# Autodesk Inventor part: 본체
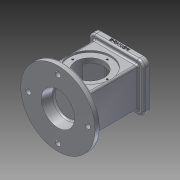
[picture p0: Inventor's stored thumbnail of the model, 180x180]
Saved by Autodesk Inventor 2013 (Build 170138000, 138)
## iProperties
Created: 2018-10
Part Number: 본체
Material: 알루미늄 6061
Document SubType Name: Modeling
Designer: Administrator
Density: 2.71 g/cm^3
Mass: 989.33 g
Surface Area: 739.56 cm^2
Volume: 365.066 cm^3
Author: Administrator
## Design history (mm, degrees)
sketch "스케치1"
  geometry: L1 (-37, -33)-(37, -33); L2 (37, -33)-(37, 33); L3 (37, 33)-(-37, 33); L4 (-37, 33)-(-37, -33); L5 (-37, -33)-(37, 33); L6 (37, -33)-(-37, 33); 1 further point
  constraints: 12 end point, 2 midpoint, 2 parallel, 1 horizontal, 1 perpendicular
  dimensions: "d1" = 74 distance of L3.end L2.end; "d2" = 66 distance of L2.end L1.end
extrude "돌출1" new body sketch "스케치1" distance "d3" = 108; taper "d4" = 0 deg
sketch "스케치2"
  geometry: L1 (37, -33)-(-37, -33) reference; L2 (37, 33)-(37, -33) reference; L3 (-37, 33)-(37, 33) reference; L4 (-37, -33)-(-37, 33) reference; C1 r 62.5 at (0, 0); 1 further point
  constraints: 1 centre point, 1 coincident
  dimensions: "d5" = 125 diameter of C1
extrude "돌출2" join sketch "스케치2" distance "d6" = 10; taper "d7" = 0 deg
sketch "스케치3"
  geometry: L1 (37, 33)-(-37, 33) reference; L2 (-37, 33)-(-37, -33) reference; L3 (-37, -33)-(37, -33) reference; L4 (37, -33)-(37, 33) reference; L5 (-46, -41)-(46, -41); L6 (46, -41)-(46, 41); L7 (46, 41)-(-46, 41); L8 (-46, 41)-(-46, -41); L9 (-46, -41)-(46, 41); L10 (46, -41)-(-46, 41); 1 further point
  constraints: 12 end point, 2 midpoint, 2 parallel, 1 horizontal, 1 perpendicular
  dimensions: "d8" = 92 distance of L7.end L6.end; "d9" = 82 distance of L6.end L5.end
extrude "돌출3" join sketch "스케치3" distance "d10" = 10; taper "d11" = 0 deg
fillet "모깎기1" dims "d12" = 10
sketch "스케치4"
  geometry: A1 r 10 centre (-36, 31) between (-36, 41) and (-46, 31) reference; A2 r 10 centre (-36, -31) between (-46, -31) and (-36, -41) reference; A3 r 10 centre (36, -31) between (36, -41) and (46, -31) reference; A4 r 10 centre (36, 31) between (46, 31) and (36, 41) reference; 5 further points
  constraints: 4 coincident
hole "구멍1" sketch "스케치4" at (-36, 31), (36, 31), (36, -31), (-36, -31) diameter "d13" = 3.242; stored, may be unused: countersink angle "d17" = 90 deg, drill point angle "d19" = 118 deg; dims "d14" = 4, "d15" = 4, "d16" = 2, "d18" = 6
sketch "스케치5"
  geometry: L1 (-26, -26)-(26, -26); L2 (26, -26)-(26, 26); L3 (26, 26)-(-26, 26); L4 (-26, 26)-(-26, -26); L5 (-26, -26)-(26, 26); L6 (26, -26)-(-26, 26); L7 (-22, -22)-(22, -22); L8 (22, -22)-(22, 22); L9 (22, 22)-(-22, 22); L10 (-22, 22)-(-22, -22); L11 (-22, -22)-(22, 22); L12 (22, -22)-(-22, 22); 1 further point
  constraints: 24 end point, 4 midpoint, 4 parallel, 2 horizontal, 2 perpendicular
  dimensions: "d20" = 52 distance of L3.end L2.end; "d21" = 52 distance of L2.end L1.end; "d22" = 44 distance of L9.end L8.end; "d23" = 44 distance of L8.end L7.end
extrude "돌출4" cut sketch "스케치5" distance "d24" = 8; taper "d25" = 0 deg
extrude "돌출5" cut sketch "스케치5" distance "d26" = 82; taper "d27" = 0 deg
sketch "스케치6"
  geometry: L1 (99.5, -10)-(-25.5, -10) reference; C1 r 35 at (37, 44); 1 further point
  constraints: 1 centre point, 1 vertical alignment
  dimensions: "d28" = 70 diameter of C1; "d29" = 54 distance from line of L1 C1.centre
extrude "돌출6" cut sketch "스케치6" distance "d30" = 3; taper "d31" = 0 deg
sketch "스케치7"
  geometry: C1 r 35 at (0, 0) reference; 2 further points
  constraints: 1 vertical alignment
  dimensions: "d32" = 29 distance of point (0, 29) C1.centre
hole "구멍2" sketch "스케치7" at (0, 29) diameter "d33" = 3.242; stored, may be unused: countersink angle "d37" = 90 deg, drill point angle "d39" = 118 deg; dims "d34" = 4, "d35" = 4, "d36" = 2, "d38" = 6
sketch "스케치8"
  geometry: L1 (62.5, -54)-(-62.5, -54) reference; C1 r 35 at (0, 0) reference; C2 r 24 at (0, 0); 1 further point
  constraints: 1 centre point, 1 coincident
  dimensions: "d44" = 48 diameter of C2 (derived); "d45" = 54 distance from line of L1 C1.centre (derived)
extrude "돌출7" cut sketch "스케치8" stored distance "d46" = 3; taper "d47" = 0 deg
sketch "스케치11"
  geometry: C1 r 62.5 at (0, 0) reference; C2 r 28 at (0, 0)
  constraints: 1 centre point, 1 coincident
  dimensions: "d49" = 56 diameter of C2 (derived)
extrude "돌출8" cut sketch "스케치11" distance "d50" = 18; taper "d51" = -10 deg
sketch "스케치12"
  geometry: L1 (37, 33)-(-37, 33) reference; L2 (0, 0)-(50, 0); C1 r 62.5 at (0, 0) reference; C2 r 4.5 at (50, 0)
  constraints: 2 end point, 1 centre point, 1 coincident, 1 parallel
  dimensions: "d54" = 50 distance of L2.start L2.end (derived); "d55" = 9 diameter of C2 (derived)
extrude "돌출9" cut sketch "스케치12" distance "d56" = 18; taper "d57" = 0 deg
chamfer "모따기1" distance "d61" = 1; stored, may be unused: second distance "d62" = 2, angle "d63" = 45 deg
fillet "모깎기2" dims "d64" = 3
fillet "모깎기4" dims "d66" = 3
fillet "모깎기5" dims "d67" = 3
fillet "모깎기6" dims "d68" = 3
fillet "모깎기7" dims "d69" = 3
sketch "스케치13"
  geometry: L1 (0, 0)-(72, 0) reference; L2 (-10, 0)-(-10, -7) reference; 2 further points
  constraints: 1 other
  dimensions: "d72" = 4 distance from line of L1 point (36, -4); "d73" = 46 distance from line of L2 point (36, -4)
feature "엠보싱1" sketch "스케치13" dims "d1" = 74, "d2" = 66, "d74" = 0.5, "d75" = 0
fillet "모깎기10" dims "d85" = 3
fillet "모깎기11" dims "d86" = 3
node "솔리드1"
pattern_circular "원형 패턴1" dims angle "d41" = 360 deg
mirror "대칭1"
pattern_circular "원형 패턴2" dims angle "d59" = 360 deg
